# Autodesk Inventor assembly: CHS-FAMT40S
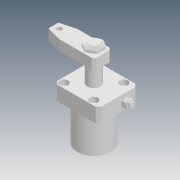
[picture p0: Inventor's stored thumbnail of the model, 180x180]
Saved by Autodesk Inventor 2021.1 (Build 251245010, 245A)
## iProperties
Created: 2019-05
Part Number: CHS-FAMT40S
Description: STEP AP203
Document SubType Name: Assembly
Designer: user
Title: chs-famt40s_asm.STEP
Revision Number: ÈÎºÎ
Sending System: SolidWorks 2017
Preprocessor: SwSTEP 2.0
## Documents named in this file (6)
- D:\Vault_2016\Projekty\Clamptek\Hydraulic\CHS\CHS-40\Inventor\CHS-FAMT40S\CHS-FAMT40S.iam
- D:\Vault_2016\Projekty\Clamptek\Hydraulic\CHS\CHS-40\Inventor\CHS-FAMT40S\CHS-FAMT40-03.ipt
- D:\Vault_2016\Projekty\Clamptek\Hydraulic\CHS\CHS-40\Inventor\CHS-FAMT40S\CHS-40S-02_3_1.ipt
- D:\Vault_2016\Projekty\Clamptek\Hydraulic\CHS\CHS-40\Inventor\CHS-FAMT40S\CHS-40S-01_3.ipt
- D:\Vault_2016\Projekty\Clamptek\Hydraulic\CHS\CHS-40\Inventor\CHS-FAMT40S\M18_3.ipt
- D:\Vault_2016\Projekty\Clamptek\Hydraulic\CHS\CHS-40\Inventor\CHS-FAMT40S\CZL10µ÷ËÙ·§_1.ipt
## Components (5 placed, 5 different names)
1. CHS-FAMT40-03_1
2. CHS-40S-02_3_1_2
3. CHS-40S-01_3_3
4. M18_3_4
5. CZL10µ÷ËÙ·§_1_5
